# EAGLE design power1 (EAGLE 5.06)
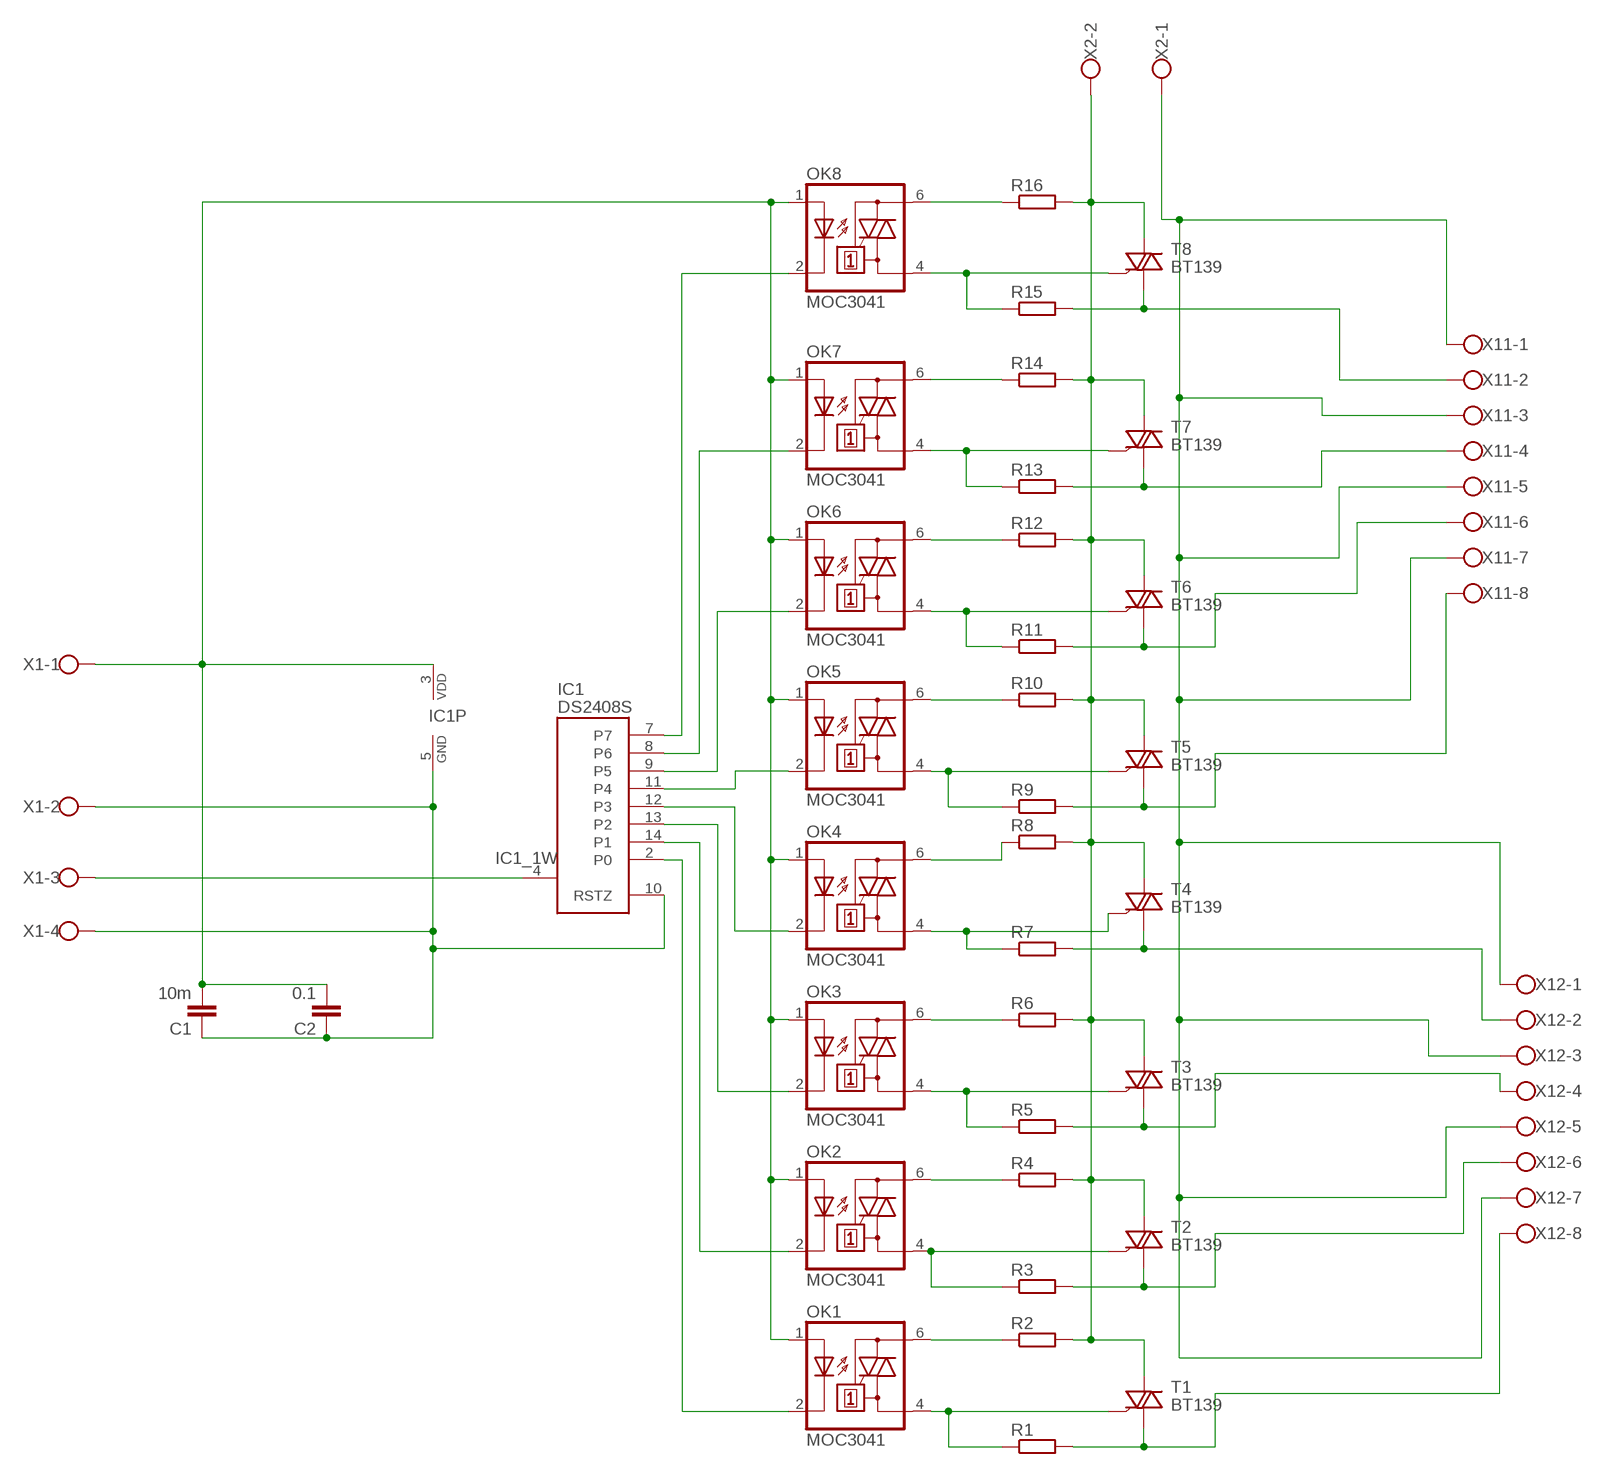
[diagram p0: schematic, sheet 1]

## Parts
C1  10m  C-EU025-025X050  [C025-025X050]
C2  0.1  C-EU025-025X050  [C025-025X050]
IC1  DS2408S  [SO16]
OK1  MOC3041  [DIL06]
OK2  MOC3041  [DIL06]
OK3  MOC3041  [DIL06]
OK4  MOC3041  [DIL06]
OK5  MOC3041  [DIL06]
OK6  MOC3041  [DIL06]
OK7  MOC3041  [DIL06]
OK8  MOC3041  [DIL06]
R1  R-EU_0204/7  [0204/7]
R2  R-EU_0204/7  [0204/7]
R3  R-EU_0204/7  [0204/7]
R4  R-EU_0204/7  [0204/7]
R5  R-EU_0204/7  [0204/7]
R6  R-EU_0204/7  [0204/7]
R7  R-EU_0204/7  [0204/7]
R8  R-EU_0204/7  [0204/7]
R9  R-EU_0204/7  [0204/7]
R10  R-EU_0204/7  [0204/7]
R11  R-EU_0204/7  [0204/7]
R12  R-EU_0204/7  [0204/7]
R13  R-EU_0204/7  [0204/7]
R14  R-EU_0204/7  [0204/7]
R15  R-EU_0204/7  [0204/7]
R16  R-EU_0204/7  [0204/7]
T1  BT139  [TO220AB_VER]
T2  BT139  [TO220AB_VER]
T3  BT139  [TO220AB_VER]
T4  BT139  [TO220AB_VER]
T5  BT139  [TO220AB_VER]
T6  BT139  [TO220AB_VER]
T7  BT139  [TO220AB_VER]
T8  BT139  [TO220AB_VER]
X1  W237-4  [W237-4]
X2  W237-102  [W237-102]
X11  W237-08P  [W237-8P]
X12  W237-08P  [W237-8P]

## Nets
N$1: C1.1 C2.1 IC1.5(GND) IC1.10(RSTZ) X1.2 X1.4
N$2: OK1.4(A1) R1.1 T1.3(G)
N$3: C1.2 C2.2 IC1.3(VDD) OK1.1(A) OK2.1(A) OK3.1(A) OK4.1(A) OK5.1(A) OK6.1(A) OK7.1(A) OK8.1(A) X1.1
N$4: IC1.2(P0) OK1.2(C)
N$5: IC1.14(P1) OK2.2(C)
N$6: IC1.13(P2) OK3.2(C)
N$7: IC1.12(P3) OK4.2(C)
N$8: IC1.11(P4) OK5.2(C)
N$9: IC1.9(P5) OK6.2(C)
N$10: IC1.8(P6) OK7.2(C)
N$11: IC1.4(1W) X1.3
N$12: OK1.6(A2) R2.1
N$13: IC1.7 OK8.2(C)
N$14: R1.2 T1.1(A1) X12.8
N$15: R2.2 R4.2 R6.2 R8.2 R10.2 R12.2 R14.2 R16.2 T1.2(A2) T2.2(A2) T3.2(A2) T4.2(A2) T5.2(A2) T6.2(A2) T7.2(A2) T8.2(A2) X2.2
N$16: OK7.6(A2) R14.1
N$17: OK2.4(A1) R3.1 T2.3(G)
N$18: OK2.6(A2) R4.1
N$19: R3.2 T2.1(A1) X12.6
N$20: OK8.4(A1) R15.1 T8.3(G)
N$21: R15.2 T8.1(A1) X11.2
N$22: OK3.4(A1) R5.1 T3.3(G)
N$23: OK3.6(A2) R6.1
N$24: R5.2 T3.1(A1) X12.4
N$26: OK8.6(A2) R16.1
N$27: OK4.4(A1) R7.1 T4.3(G)
N$28: OK4.6(A2) R8.1
N$29: R7.2 T4.1(A1) X12.2
N$30: X2.1 X11.1 X11.3 X11.5 X11.7 X12.1 X12.3 X12.5 X12.7
N$33: OK5.4(A1) R9.1 T5.3(G)
N$34: R9.2 T5.1(A1) X11.8
N$37: OK5.6(A2) R10.1
N$38: OK6.4(A1) R11.1 T6.3(G)
N$39: R11.2 T6.1(A1) X11.6
N$42: OK6.6(A2) R12.1
N$43: OK7.4(A1) R13.1 T7.3(G)
N$44: R13.2 T7.1(A1) X11.4

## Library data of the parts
C1 C2 = resistor:C-EU: CAPACITOR, European symbol
IC1 = 1wire:DS2408: 8-Channel Addressable Switch This is a general purpose I/O multiplier. The PIO pins P0..P7 are inputs/open drain outputs and can be used in a mixed I/O fashion. Output sink capability is appr. 4mA. Each input state can be read but changing input signals additionally trigger the egde detector for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
OK1-OK8 = tdg:MOC3041: SIEMENS OPTO COUPLER
R1-R16 = resistor:R-EU_: RESISTOR, European symbol
T1-T8 = tdg:BT139: Triac BT136 series E sensitive gate Source: http://www.nxp.com/acrobat_download/datasheets/BT136_SERIES_E_2.pdf
X1 = con-wago-500:W237-4: WAGO SCREW CLAMP
X2 = con-wago-500:W237-102: WAGO SCREW CLAMP
X11 X12 = con-wago-508:W237-08P: WAGO SREW CLAMP

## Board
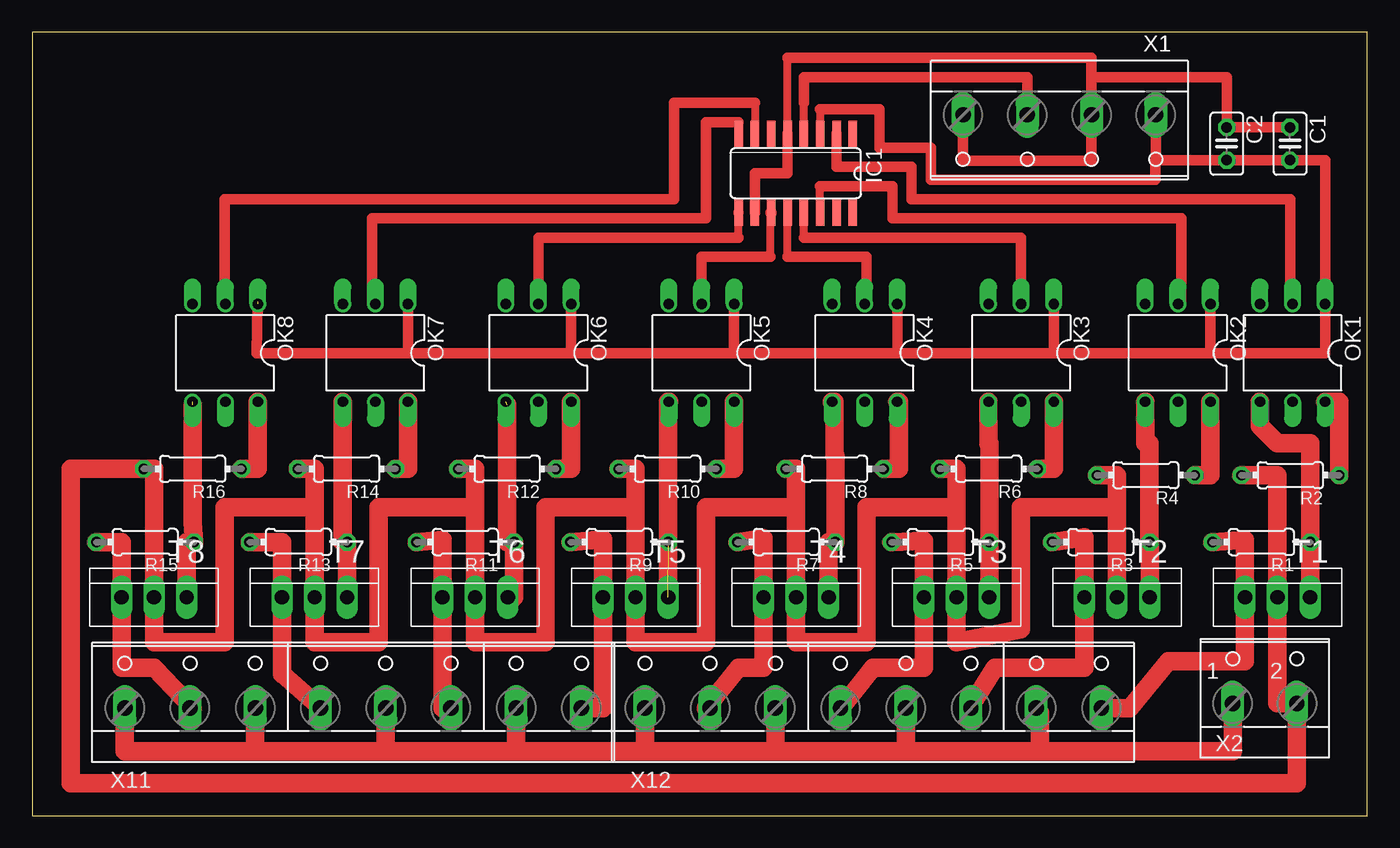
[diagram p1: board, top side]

Size 104 x 61 mm. Coordinates in mm from the lower left corner, seen from the top.
Outline: 0,0 104,0 104,61 0,61 0,0
Copper layers (1*16): Top 0.035mm / dielectric 1.5mm / Bottom 0.035mm
Design rules "default": minimum track width 10mil, minimum drill 24mil, track to track 8mil, track to pad 8mil, pad to pad 8mil, via to via 8mil, smd to smd 8mil, copper to edge 40mil, drill to drill 8mil, minimum pad ring 10mil, minimum via ring 8mil, stop-mask expansion 4mil, vias tented up to drill 0mil, thermal gap 10mil

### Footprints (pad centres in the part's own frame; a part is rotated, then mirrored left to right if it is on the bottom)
C025-025X050 = drill 0.813 octagon: 1 -1.27,0; 2 1.27,0
SO16 = smd 0.66 x 2.032: 1 -4.445,-3.073; 2 -3.175,-3.073; 3 -1.905,-3.073; 4 -0.635,-3.073; 5 0.635,-3.073; 6 1.905,-3.073; 7 3.175,-3.073; 8 4.445,-3.073; 9 4.445,3.073; 10 3.175,3.073; 11 1.905,3.073; 12 0.635,3.073; 13 -0.635,3.073; 14 -1.905,3.073; 15 -3.175,3.073; 16 -4.445,3.073
DIL06 = drill 0.813 offset: 1 -2.54,-3.81; 2 0,-3.81; 3 2.54,-3.81; 4 2.54,3.81; 5 0,3.81; 6 -2.54,3.81
0204/7 = drill 0.813 octagon: 1 -3.81,0; 2 3.81,0
TO220AB_VER = drill 1.118 long: 1 -2.54,0; 2 0,0; 3 2.54,0
W237-4 = drill 1.194 long: 1 -7.5,-1.27; 2 -2.5,-1.27; 3 2.5,-1.27; 4 7.5,-1.27
W237-102 = drill 1.194 long: 1 -2.5,-1.27; 2 2.5,-1.27
W237-8P = drill 1.194 long: 1 -17.78,-0.635; 2 -12.7,-0.635; 3 -7.62,-0.635; 4 -2.54,-0.635; 5 2.54,-0.635; 6 7.62,-0.635; 7 12.7,-0.635; 8 17.78,-0.635

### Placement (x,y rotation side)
C1  97.97,52.31 270 top
C2  93.04,52.31 270 top
IC1  59.47,50.01 180 top
OK1  98.17,36.03 180 top
OK2  89.24,36.03 180 top
OK3  77.04,36.03 180 top
OK4  64.84,36.03 180 top
OK5  52.14,36.03 180 top
OK6  39.44,36.03 180 top
OK7  26.74,36.03 180 top
OK8  15.04,36.03 180 top
R1  95.74,21.3 180 top
R2  98,26.5 180 top
R3  83.24,21.3 180 top
R4  86.75,26.5 180 top
R5  70.74,21.3 180 top
R6  74.5,27 180 top
R7  58.74,21.3 180 top
R8  62.5,27 180 top
R9  45.74,21.3 180 top
R10  49.5,27 180 top
R11  33.74,21.3 180 top
R12  37,27 180 top
R13  20.74,21.3 180 top
R14  24.5,27 180 top
R15  8.81,21.3 180 top
R16  12.5,27 180 top
T1  97,17 0 top
T2  84.5,17 0 top
T3  72,17 0 top
T4  59.5,17 0 top
T5  47,17 0 top
T6  34.5,17 0 top
T7  22,17 0 top
T8  9.5,17 0 top
X1  80.01,53.29 180 top
X2  96,10 0 top
X11  25,9 0 top
X12  65.5,9 0 top

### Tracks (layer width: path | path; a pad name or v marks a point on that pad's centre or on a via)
N$1  (1 unrouted)
  Top 0.61: IC1.5 58.84,59
  Top 0.813: C1.1 C2.1 93.04,57.5 82.5,57.5 | IC1.5 58.84,50 56.3,50 IC1.10 | 82.5,57.5 X1.2 82.51,59 58.84,59 | 82.5,57.5 82.5,52.5 | 82.5,52.5 82.5,52 | X1.4 72.5,51 82.5,51 82.5,52.5
N$2
  Top 1.422: T1.3 R1.1 99.55,29 97,29 95.63,30.37 OK1.4
N$3  (1 unrouted)
  Top 0.61: 61.38,55 IC1.3
  Top 0.813: 87.51,51.04 X1.1 | C2.2 87.51,51.04 | C2.2 C1.2 | C2.2 100.71,51.04 OK1.1 100.71,36 91.78,36 | 61.38,55 66,55 66,52 70,52 70,49.5 87.5,49.5 87.5,51.04 87.51,51.04 | 29.5,36 17.5,36 17.58,40 | 29.5,36 41.5,36 | 41.5,36 42,36 | 42,36 55,36 | 79.58,36 90.5,36 91.78,36 | OK7.1 29.28,36 29.5,36 | 41.5,36 41.48,36 | OK5.1 54.68,36 55,36 | 67.38,36 OK4.1 | 55,36 67.38,36 | 79.58,36 OK3.1 | 67.38,36 79.58,36 | 91.78,36 OK2.1 | OK6.1 41.98,36 42,36
N$4
  Top 0.813: IC1.2 62.65,50.5 68.5,50.5 68.5,48 98,48 98,39.84 OK1.2
N$5
  Top 0.61: IC1.14 61.38,49
  Top 0.813: 61.38,49 67,49 67,46.5 89.5,46.5 89.5,39.84 OK2.2
N$6
  Top 0.61: 60.11,45 IC1.13
  Top 0.813: 60.11,45 77,45 77,39.84 OK3.2
N$7
  Top 0.61: 58.84,43.5 IC1.12
  Top 0.813: 58.84,43.5 65,43.5 65,39.84 OK4.2
N$8
  Top 0.61: 57.5,43.5 57.5,46.94
  Top 0.813: OK5.2 52.14,43.5 57.5,43.5 | 57.5,46.94 IC1.11
N$9
  Top 0.61: 55,45 55,46.94
  Top 0.813: OK6.2 39.44,45 55,45 | 55,46.94 IC1.9
N$10
  Top 0.61: 55.03,54 IC1.8
  Top 0.813: 55.03,54 52.5,54 52.5,46.5 26.5,46.5 26.5,39.84 OK7.2
N$11
  Top 0.61: IC1.4 60.11,55.5
  Top 0.813: X1.3 77.51,57.5 60.11,57.5 60.11,55.5
N$12
  Top 1.422: R2.1 101.81,32.22 OK1.6
N$13
  Top 0.61: 56.3,55.5 IC1.7
  Top 0.813: 56.3,55.5 50,55.5 50,48 15,48 15,39.84 OK8.2
N$14
  Top 1.422: R1.2 94.46,21.48 T1.1 94.46,12 88.5,12 85.5,8.37 X12.8
N$15
  Top 1.422: 22,24 T7.2 22,13.5 27,13.5 27,24 34.5,24 | 22,24 22,27 R14.2 | 34.5,24 T6.2 34.5,13.5 40,13.5 40,24 47,24 | 34.5,24 34.5,27 R12.2 | 47,24 47,17.5 | 47,24 47,27 R10.2 | 47,17.5 T5.2 | 59.5,27 T4.2 59.5,13.5 65,13.5 65,24 72,24 72,27 | 59.5,27 R8.2 | 72,27 T3.2 72,13.5 77,14.5 77,24 84.5,24 | 72,27 R6.2 | 84.5,24 T2.2 | R4.2 84.5,26.5 84.5,24 | R2.2 97,26.5 T1.2 97,8.73 X2.2 98.5,2.5 3,2.5 3,27 R16.2 9.5,27 T8.2 9.5,13.5 15,13.5 15,24 22,24 | 59.5,27 59.5,24 52.5,24 52.5,13.5 47,13.5 47,17.5
N$16
  Top 1.422: R14.1 29.28,27 OK7.6
N$17
  Top 1.422: T2.3 R3.1 87,21.3 87,29 86.7,29 OK2.4
N$18
  Top 1.422: R4.1 91.78,26.5 OK2.6
N$19
  Top 1.422: R3.2 81.96,21.68 T2.1 81.96,11.5 75,11.5 73,8.37 X12.6
N$20  (1 unrouted)
  Top 1.422: T8.3 12.04,21.29 R15.1 12.5,22.79 12.5,32
N$21
  Top 1.422: R15.2 6.96,21.29 T8.1 6.96,11.5 9.5,11.5 12.5,8.37 X11.2
N$22
  Top 1.422: T3.3 R5.1 74.55,29 74.5,29 OK3.4
N$23
  Top 1.422: R6.1 79.58,27 OK3.6
N$24
  Top 1.422: R5.2 69.46,21.38 T3.1 69.46,11.5 65.5,11.5 63,8.37 X12.4
N$26
  Top 1.422: OK8.6 17.58,27 R16.1
N$27
  Top 1.422: OK4.4 62.5,32.22 62.5,28 62.55,28 R7.1 62.04,21.3 T4.3
N$28
  Top 1.422: R8.1 67.5,27 67.5,32.22 OK4.6
N$29
  Top 1.422: R7.2 56.96,21.58 T4.1 56.96,11.5 55,11.5 52.5,8.37 X12.2
N$30
  Top 1.422: X11.1 7.22,5 17.5,5 | 17.5,5 28,5 | 28,5 38,5 | 38,5 48,5 | 48,5 58.5,5 | 58.5,5 68.5,5 | 68.5,5 78.5,5 | 78.5,5 93.5,5 X2.1 | X11.3 17.38,5 17.5,5 | X11.5 27.54,5 28,5 | X11.7 37.7,5 38,5 | X12.1 47.72,5 48,5 | X12.3 57.88,5 58.5,5 | X12.5 68.04,5 68.5,5 | X12.7 78.2,8 78.5,8 78.5,5
N$33  (1 unrouted)
  Top 1.422: T5.3 49.54,32.22 OK5.4
N$34
  Top 1.422: R9.2 44.46,21.51 T5.1 44.46,8.37 X11.8
N$37
  Top 1.422: OK5.6 54.68,27 R10.1
N$38  (1 unrouted)
  Top 1.422: T6.3 37.55,17 R11.1 37,21.3 37,32
N$39
  Top 1.422: R11.2 31.96,21.48 T6.1 31.96,8.37 X11.6
N$42
  Top 1.422: OK6.6 41.98,27 R12.1
N$43
  Top 1.422: T7.3 R13.1 24.2,21.3 OK7.4
N$44
  Top 1.422: R13.2 19.46,21.29 T7.1 19.46,11 19.5,11 22.5,8.37 X11.4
